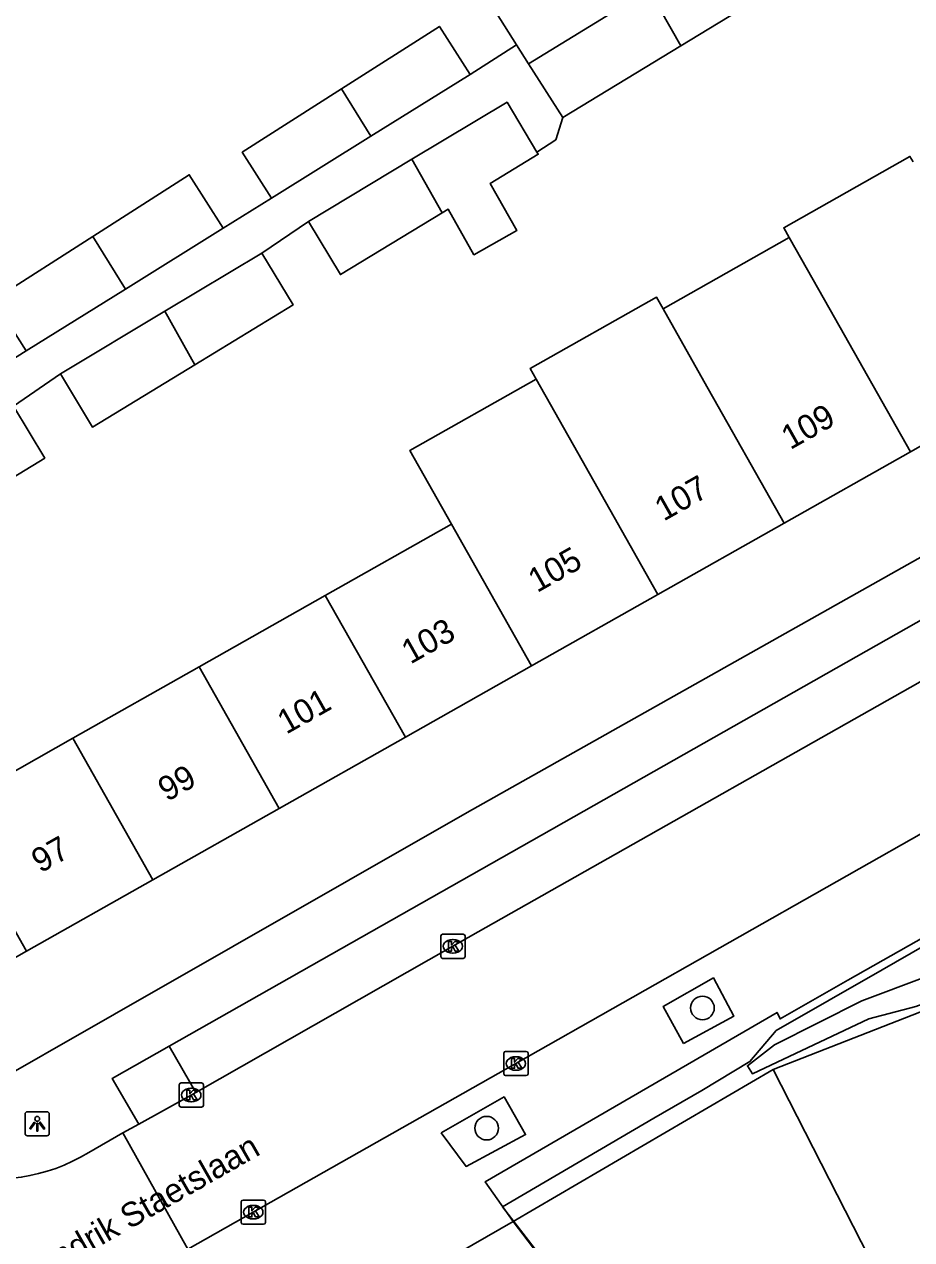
# Model space of a CAD drawing. Extents: x 160037 to 160839, y 385326 to 386441.
# Drawn here: x 160357.7 to 160394.4, y 386036.4 to 386086.7 of the extents above; entities that cross this region are included whole.
import ezdxf

# ---------------------------------------------------------------- set-up
doc = ezdxf.new("R2010")
doc.units = 0
for name, color, linetype in [('IMGEO_Boom', 7, 'Continuous'), ('IMGEO_Haag', 7, 'Continuous'), ('IMGEO_Hek', 7, 'Continuous'), ('IMGEO_Kolk', 7, 'Continuous'), ('IMGEO_Lichtpunt', 7, 'Continuous'), ('IMGEO_Openbare_ruimte_label', 7, 'Continuous'), ('IMGEO_Pand', 7, 'Continuous'), ('IMGEO_Pand_nummerreeks', 7, 'Continuous'), ('IMGEO_Parkeervlak_open', 7, 'Continuous'), ('IMGEO_Rijbaan_lokaal_open', 7, 'Continuous'), ('IMGEO_Voetpad_gesloten', 7, 'Continuous'), ('IMGEO_Voetpad_open', 7, 'Continuous')]:
    doc.layers.add(name, color=color, linetype=linetype)

msp = doc.modelspace()

# ---------------------------------------------------------------- linework, layer by layer
at = {"layer": 'IMGEO_Boom'}
for centre in [(160385.758, 386045.992), (160376.83, 386041.02)]:
    msp.add_circle(centre, 0.489, dxfattribs=at)
at = {"layer": 'IMGEO_Haag'}
msp.add_lwpolyline([(160392.649, 386045.543), (160387.824, 386043.274), (160387.621, 386043.599), (160388.74, 386044.465), (160392.347, 386046.283), (160394.958, 386047.267), (160402.134, 386049.961), (160402.701, 386049.05), (160394.581, 386046.056), (160392.649, 386045.543)], dxfattribs=at)
at = {"layer": 'IMGEO_Hek'}
msp.add_lwpolyline([(160401.535, 386052.361), (160401.401, 386052.286), (160393.193, 386047.572), (160388.813, 386045.056), (160387.724, 386043.771), (160385.731, 386042.581), (160383.749, 386041.433), (160377.491, 386037.764), (160380.288, 386034.138), (160388.002, 386023.963)], dxfattribs=at)
at = {"layer": 'IMGEO_Kolk'}
for p, q in [((160374.934, 386048.119), (160374.934, 386048.971)), ((160375.009, 386049.045), (160375.861, 386049.045)), ((160375.422, 386048.825), (160375.447, 386048.825)), ((160375.935, 386048.971), (160375.935, 386048.119)), ((160375.445, 386048.265), (160375.42, 386048.265)), ((160375.861, 386048.045), (160375.009, 386048.045)), ((160377.616, 386044.195), (160378.468, 386044.195)), ((160377.541, 386043.269), (160377.541, 386044.121)), ((160378.029, 386043.975), (160378.054, 386043.975)), ((160378.542, 386044.121), (160378.542, 386043.269)), ((160378.468, 386043.195), (160377.616, 386043.195)), ((160378.052, 386043.415), (160378.027, 386043.415)), ((160364.11, 386041.964), (160364.11, 386042.816)), ((160364.185, 386042.89), (160365.037, 386042.89)), ((160364.598, 386042.67), (160364.623, 386042.67)), ((160365.111, 386042.816), (160365.111, 386041.964)), ((160365.037, 386041.89), (160364.185, 386041.89)), ((160364.621, 386042.11), (160364.596, 386042.11)), ((160366.675, 386037.119), (160366.675, 386037.971)), ((160366.75, 386038.045), (160367.602, 386038.045)), ((160367.163, 386037.825), (160367.188, 386037.825)), ((160367.676, 386037.971), (160367.676, 386037.119)), ((160367.186, 386037.265), (160367.161, 386037.265)), ((160367.602, 386037.045), (160366.75, 386037.045))]:
    msp.add_line(p, q, dxfattribs=at)
for points in [[(160374.934, 386048.119), (160374.934, 386048.971)], [(160375.009, 386049.045), (160375.861, 386049.045)], [(160375.255, 386048.745), (160375.378, 386048.745), (160375.378, 386048.594), (160375.508, 386048.745), (160375.672, 386048.745), (160375.526, 386048.594), (160375.679, 386048.345), (160375.527, 386048.345), (160375.442, 386048.509), (160375.378, 386048.442), (160375.378, 386048.345), (160375.255, 386048.345), (160375.255, 386048.745)], [(160375.935, 386048.971), (160375.935, 386048.119)], [(160375.861, 386048.045), (160375.009, 386048.045)], [(160377.616, 386044.195), (160378.468, 386044.195)], [(160377.541, 386043.269), (160377.541, 386044.121)], [(160377.862, 386043.895), (160377.985, 386043.895), (160377.985, 386043.744), (160378.115, 386043.895), (160378.279, 386043.895), (160378.133, 386043.744), (160378.286, 386043.495), (160378.134, 386043.495), (160378.049, 386043.659), (160377.985, 386043.592), (160377.985, 386043.495), (160377.862, 386043.495), (160377.862, 386043.895)], [(160378.542, 386044.121), (160378.542, 386043.269)], [(160378.468, 386043.195), (160377.616, 386043.195)], [(160364.11, 386041.964), (160364.11, 386042.816)], [(160364.185, 386042.89), (160365.037, 386042.89)], [(160365.111, 386042.816), (160365.111, 386041.964)], [(160364.431, 386042.59), (160364.554, 386042.59), (160364.554, 386042.439), (160364.684, 386042.59), (160364.848, 386042.59), (160364.702, 386042.439), (160364.855, 386042.19), (160364.703, 386042.19), (160364.618, 386042.354), (160364.554, 386042.287), (160364.554, 386042.19), (160364.431, 386042.19), (160364.431, 386042.59)], [(160365.037, 386041.89), (160364.185, 386041.89)], [(160366.675, 386037.119), (160366.675, 386037.971)], [(160366.75, 386038.045), (160367.602, 386038.045)], [(160366.996, 386037.745), (160367.119, 386037.745), (160367.119, 386037.594), (160367.249, 386037.745), (160367.413, 386037.745), (160367.267, 386037.594), (160367.42, 386037.345), (160367.268, 386037.345), (160367.183, 386037.509), (160367.119, 386037.442), (160367.119, 386037.345), (160366.996, 386037.345), (160366.996, 386037.745)], [(160367.676, 386037.971), (160367.676, 386037.119)], [(160367.602, 386037.045), (160366.75, 386037.045)]]:
    msp.add_lwpolyline(points, dxfattribs=at)
for centre, start, end in [((160375.011, 386048.969), 91.552, 178.448), ((160375.011, 386048.969), 91.552, 178.448), ((160375.859, 386048.969), 1.552, 88.448), ((160375.859, 386048.969), 1.552, 88.448), ((160375.011, 386048.121), 181.552, 268.448), ((160375.011, 386048.121), 181.552, 268.448), ((160375.859, 386048.121), 271.552, 358.448), ((160375.859, 386048.121), 271.552, 358.448), ((160377.618, 386044.119), 91.552, 178.448), ((160377.618, 386044.119), 91.552, 178.448), ((160378.466, 386044.119), 1.552, 88.448), ((160378.466, 386044.119), 1.552, 88.448), ((160377.618, 386043.271), 181.552, 268.448), ((160377.618, 386043.271), 181.552, 268.448), ((160378.466, 386043.271), 271.552, 358.448), ((160378.466, 386043.271), 271.552, 358.448), ((160364.187, 386042.814), 91.552, 178.448), ((160364.187, 386042.814), 91.552, 178.448), ((160365.035, 386042.814), 1.552, 88.448), ((160365.035, 386042.814), 1.552, 88.448), ((160364.187, 386041.966), 181.552, 268.448), ((160364.187, 386041.966), 181.552, 268.448), ((160365.035, 386041.966), 271.552, 358.448), ((160365.035, 386041.966), 271.552, 358.448), ((160366.752, 386037.969), 91.552, 178.448), ((160366.752, 386037.969), 91.552, 178.448), ((160367.6, 386037.969), 1.552, 88.448), ((160367.6, 386037.969), 1.552, 88.448), ((160366.752, 386037.121), 181.552, 268.448), ((160366.752, 386037.121), 181.552, 268.448), ((160367.6, 386037.121), 271.552, 358.448), ((160367.6, 386037.121), 271.552, 358.448)]:
    msp.add_arc(centre, 0.0765, start, end, dxfattribs=at)
for centre, major_axis, ratio, start_param, end_param in [((160375.421, 386048.545), (-0.387, 0.002), 0.722429, 4.712389, 7.853982), ((160375.446, 386048.545), (-0.39, 0.002), 0.717154, 1.570796, 4.712389), ((160378.028, 386043.695), (-0.387, 0.002), 0.722429, 4.712389, 7.853982), ((160378.053, 386043.695), (-0.39, 0.002), 0.717154, 1.570796, 4.712389), ((160364.597, 386042.39), (-0.387, 0.002), 0.722429, 4.712389, 7.853982), ((160364.622, 386042.39), (-0.39, 0.002), 0.717154, 1.570796, 4.712389), ((160367.162, 386037.545), (-0.387, 0.002), 0.722429, 4.712389, 7.853982), ((160367.187, 386037.545), (-0.39, 0.002), 0.717154, 1.570796, 4.712389)]:
    msp.add_ellipse(centre, major_axis=major_axis, ratio=ratio, start_param=start_param, end_param=end_param, dxfattribs=at)
at = {"layer": 'IMGEO_Lichtpunt'}
for p, q in [((160358.639, 386041.702), (160357.831, 386041.702)), ((160358.639, 386041.702), (160357.831, 386041.702)), ((160357.737, 386041.607), (160357.737, 386040.8)), ((160357.737, 386041.607), (160357.737, 386040.8)), ((160358.733, 386040.8), (160358.733, 386041.607)), ((160358.733, 386040.8), (160358.733, 386041.607)), ((160357.831, 386040.706), (160358.639, 386040.706)), ((160357.831, 386040.706), (160358.639, 386040.706))]:
    msp.add_line(p, q, dxfattribs=at)
for points in [[(160358.111, 386041.271), (160358.15, 386041.243), (160357.962, 386040.981), (160357.924, 386041.008), (160358.111, 386041.271)], [(160358.213, 386041.223), (160358.26, 386041.223), (160358.26, 386040.901), (160358.213, 386040.901), (160358.213, 386041.223)], [(160358.323, 386041.243), (160358.361, 386041.27), (160358.548, 386041.008), (160358.509, 386040.98), (160358.323, 386041.243)]]:
    msp.add_lwpolyline(points, dxfattribs=at)
msp.add_circle((160358.236, 386041.405), 0.0994, dxfattribs=at)
for centre, start, end in [((160357.831, 386041.607), 90, 180), ((160357.831, 386041.607), 90, 180), ((160358.639, 386041.607), 0, 90), ((160358.639, 386041.607), 0, 90), ((160357.831, 386040.8), 180, 270), ((160357.831, 386040.8), 180, 270), ((160358.639, 386040.8), 270, 0), ((160358.639, 386040.8), 270, 360)]:
    msp.add_arc(centre, 0.0946, start, end, dxfattribs=at)
at = {"layer": 'IMGEO_Pand'}
for points in [[(160381.172, 386090.019), (160377.071, 386087.402), (160378.068, 386085.839)], [(160384.867, 386085.801), (160388.028, 386087.724), (160386.919, 386089.572)], [(160383.559, 386088.116), (160384.867, 386085.801)], [(160378.567, 386085.056), (160382.684, 386087.579)], [(160376.142, 386084.612), (160374.876, 386086.598), (160370.822, 386084.012)], [(160378.567, 386085.056), (160378.068, 386085.839)], [(160379.986, 386082.832), (160384.867, 386085.801)], [(160379.986, 386082.832), (160378.567, 386085.056)], [(160372.035, 386082.054), (160376.142, 386084.612)], [(160370.822, 386084.012), (160366.718, 386081.393), (160367.929, 386079.496)], [(160370.822, 386084.012), (160372.035, 386082.054)], [(160373.74, 386081.1), (160377.673, 386083.459), (160378.908, 386081.402)], [(160372.035, 386082.054), (160367.929, 386079.496)], [(160374.99, 386078.889), (160375.234, 386079.038), (160376.301, 386077.151), (160378.073, 386078.153), (160376.974, 386080.096), (160378.965, 386081.307), (160378.908, 386081.402)], [(160369.458, 386078.531), (160373.74, 386081.1)], [(160373.74, 386081.1), (160374.99, 386078.889)], [(160394.471, 386080.999), (160394.344, 386081.223), (160389.122, 386078.27), (160389.351, 386077.865)], [(160365.93, 386078.251), (160364.523, 386080.458), (160360.53, 386077.911)], [(160374.99, 386078.889), (160370.781, 386076.328), (160369.458, 386078.531)], [(160360.53, 386077.911), (160356.424, 386075.292), (160357.776, 386073.171)], [(160360.53, 386077.911), (160361.882, 386075.729)], [(160361.882, 386075.729), (160365.93, 386078.251)], [(160384.128, 386074.911), (160389.351, 386077.865)], [(160389.351, 386077.865), (160391.045, 386074.87), (160394.362, 386069.004)], [(160367.534, 386077.224), (160363.513, 386074.812)], [(160364.761, 386072.603), (160368.824, 386075.075), (160367.534, 386077.224)], [(160361.882, 386075.729), (160357.776, 386073.171)], [(160378.876, 386072.01), (160378.63, 386072.445), (160383.853, 386075.398), (160384.128, 386074.911)], [(160384.128, 386074.911), (160385.822, 386071.916), (160389.138, 386066.052)], [(160359.198, 386072.224), (160363.513, 386074.812)], [(160363.513, 386074.812), (160364.761, 386072.603)], [(160359.198, 386072.224), (160360.52, 386070.023), (160364.761, 386072.603)], [(160375.376, 386066.009), (160373.653, 386069.056), (160378.876, 386072.01)], [(160383.914, 386063.1), (160380.599, 386068.963), (160378.876, 386072.01)], [(160394.362, 386069.004), (160399.584, 386071.956)], [(160354.54, 386066.3), (160358.55, 386068.739), (160357.26, 386070.889)], [(160394.362, 386069.004), (160389.138, 386066.052)], [(160370.154, 386063.056), (160375.376, 386066.009)], [(160375.376, 386066.009), (160378.691, 386060.148)], [(160389.138, 386066.052), (160383.914, 386063.1)], [(160364.931, 386060.102), (160370.154, 386063.056)], [(160370.154, 386063.056), (160373.467, 386057.196)], [(160383.914, 386063.1), (160378.691, 386060.148)], [(160359.708, 386057.149), (160364.931, 386060.102)], [(160368.244, 386054.244), (160364.931, 386060.102)], [(160378.691, 386060.148), (160373.467, 386057.196)], [(160354.485, 386054.195), (160359.708, 386057.149)], [(160359.708, 386057.149), (160363.02, 386051.292)], [(160373.467, 386057.196), (160368.244, 386054.244)], [(160368.244, 386054.244), (160363.02, 386051.292)], [(160357.796, 386048.34), (160352.469, 386045.329), (160349.158, 386051.183), (160354.485, 386054.195)], [(160354.485, 386054.195), (160357.796, 386048.34)], [(160363.02, 386051.292), (160357.796, 386048.34)]]:
    msp.add_lwpolyline(points, dxfattribs=at)
at = {"layer": 'IMGEO_Parkeervlak_open'}
msp.add_lwpolyline([(160363.692, 386044.414), (160364.805, 386042.494)], dxfattribs=at)
at = {"layer": 'IMGEO_Rijbaan_lokaal_open'}
for points in [[(160412.763, 386069.687), (160398.447, 386061.56), (160375.435, 386048.545), (160364.805, 386042.494)], [(160415.363, 386064.833), (160400.173, 386056.238), (160378.042, 386043.695), (160367.176, 386037.545), (160364.472, 386036.019)], [(160364.805, 386042.494), (160364.611, 386042.39), (160362.434, 386041.192)], [(160361.775, 386040.825), (160362.434, 386041.192)], [(160360.365, 386040.013), (160361.775, 386040.825)], [(160361.775, 386040.825), (160364.472, 386036.019)]]:
    msp.add_lwpolyline(points, dxfattribs=at)
msp.add_arc((160356.41, 386046.506), 7.602, 212.706, 301.346, dxfattribs=at)
at = {"layer": 'IMGEO_Voetpad_gesloten'}
for points in [[(160388.683, 386043.452), (160402.908, 386049.002), (160403.082, 386049.07)], [(160395.783, 386033.199), (160394.307, 386032.431), (160388.683, 386043.452)]]:
    msp.add_lwpolyline(points, dxfattribs=at)
at = {"layer": 'IMGEO_Voetpad_open'}
for points in [[(160378.068, 386085.839), (160376.142, 386084.612)], [(160378.908, 386081.402), (160379.698, 386081.912), (160379.986, 386082.832)], [(160367.929, 386079.496), (160365.93, 386078.251)], [(160367.534, 386077.224), (160369.458, 386078.531)], [(160413.098, 386074.945), (160376.029, 386054.076), (160361.429, 386045.73), (160355.592, 386042.393)], [(160357.776, 386073.171), (160355.758, 386071.914)], [(160357.26, 386070.889), (160359.198, 386072.224)], [(160363.692, 386044.414), (160395.836, 386062.628), (160412.593, 386072.071)], [(160377.931, 386037.165), (160376.77, 386038.805), (160388.848, 386045.805), (160388.971, 386045.536), (160391.768, 386047.141), (160401.407, 386052.589)], [(160384.971, 386044.516), (160384.134, 386046.054), (160386.211, 386047.233), (160387.061, 386045.654), (160384.971, 386044.516)], [(160362.434, 386041.192), (160361.339, 386043.078), (160363.692, 386044.414)], [(160377.931, 386037.165), (160388.683, 386043.452)], [(160374.945, 386040.822), (160377.549, 386042.312), (160378.439, 386040.755), (160375.978, 386039.435), (160374.945, 386040.822)], [(160371.309, 386033.359), (160377.931, 386037.165)], [(160377.931, 386037.165), (160388.002, 386023.963)]]:
    msp.add_lwpolyline(points, dxfattribs=at)

# ---------------------------------------------------------------- texts
at = {"layer": 'IMGEO_Openbare_ruimte_label'}
msp.add_text('Hendrik Staetslaan', height=1, rotation=29.7449, dxfattribs=at).set_placement((160357.717, 386034.351))
at = {"layer": 'IMGEO_Pand_nummerreeks'}
for s, rotation, p in [('109', 29.4443, (160389.391, 386069.065)), ('107', 29.4443, (160384.154, 386066.108)), ('105', 29.4443, (160378.916, 386063.152)), ('103', 29.4444, (160373.677, 386060.195)), ('101', 29.4444, (160368.54, 386057.294)), ('99', 29.4444, (160363.604, 386054.508)), ('97', 29.4444, (160358.367, 386051.551))]:
    msp.add_text(s, height=1, rotation=rotation, dxfattribs=at).set_placement(p)

doc.saveas('drawing.dxf')
